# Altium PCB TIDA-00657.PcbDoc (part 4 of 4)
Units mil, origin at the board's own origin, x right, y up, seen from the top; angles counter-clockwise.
Board outline 2500 x 2500 mil, 4 copper layers (Top Layer, MidLayer1, MidLayer2, Bottom Layer); 149 components, 57 nets, 332 pads, 124 vias.
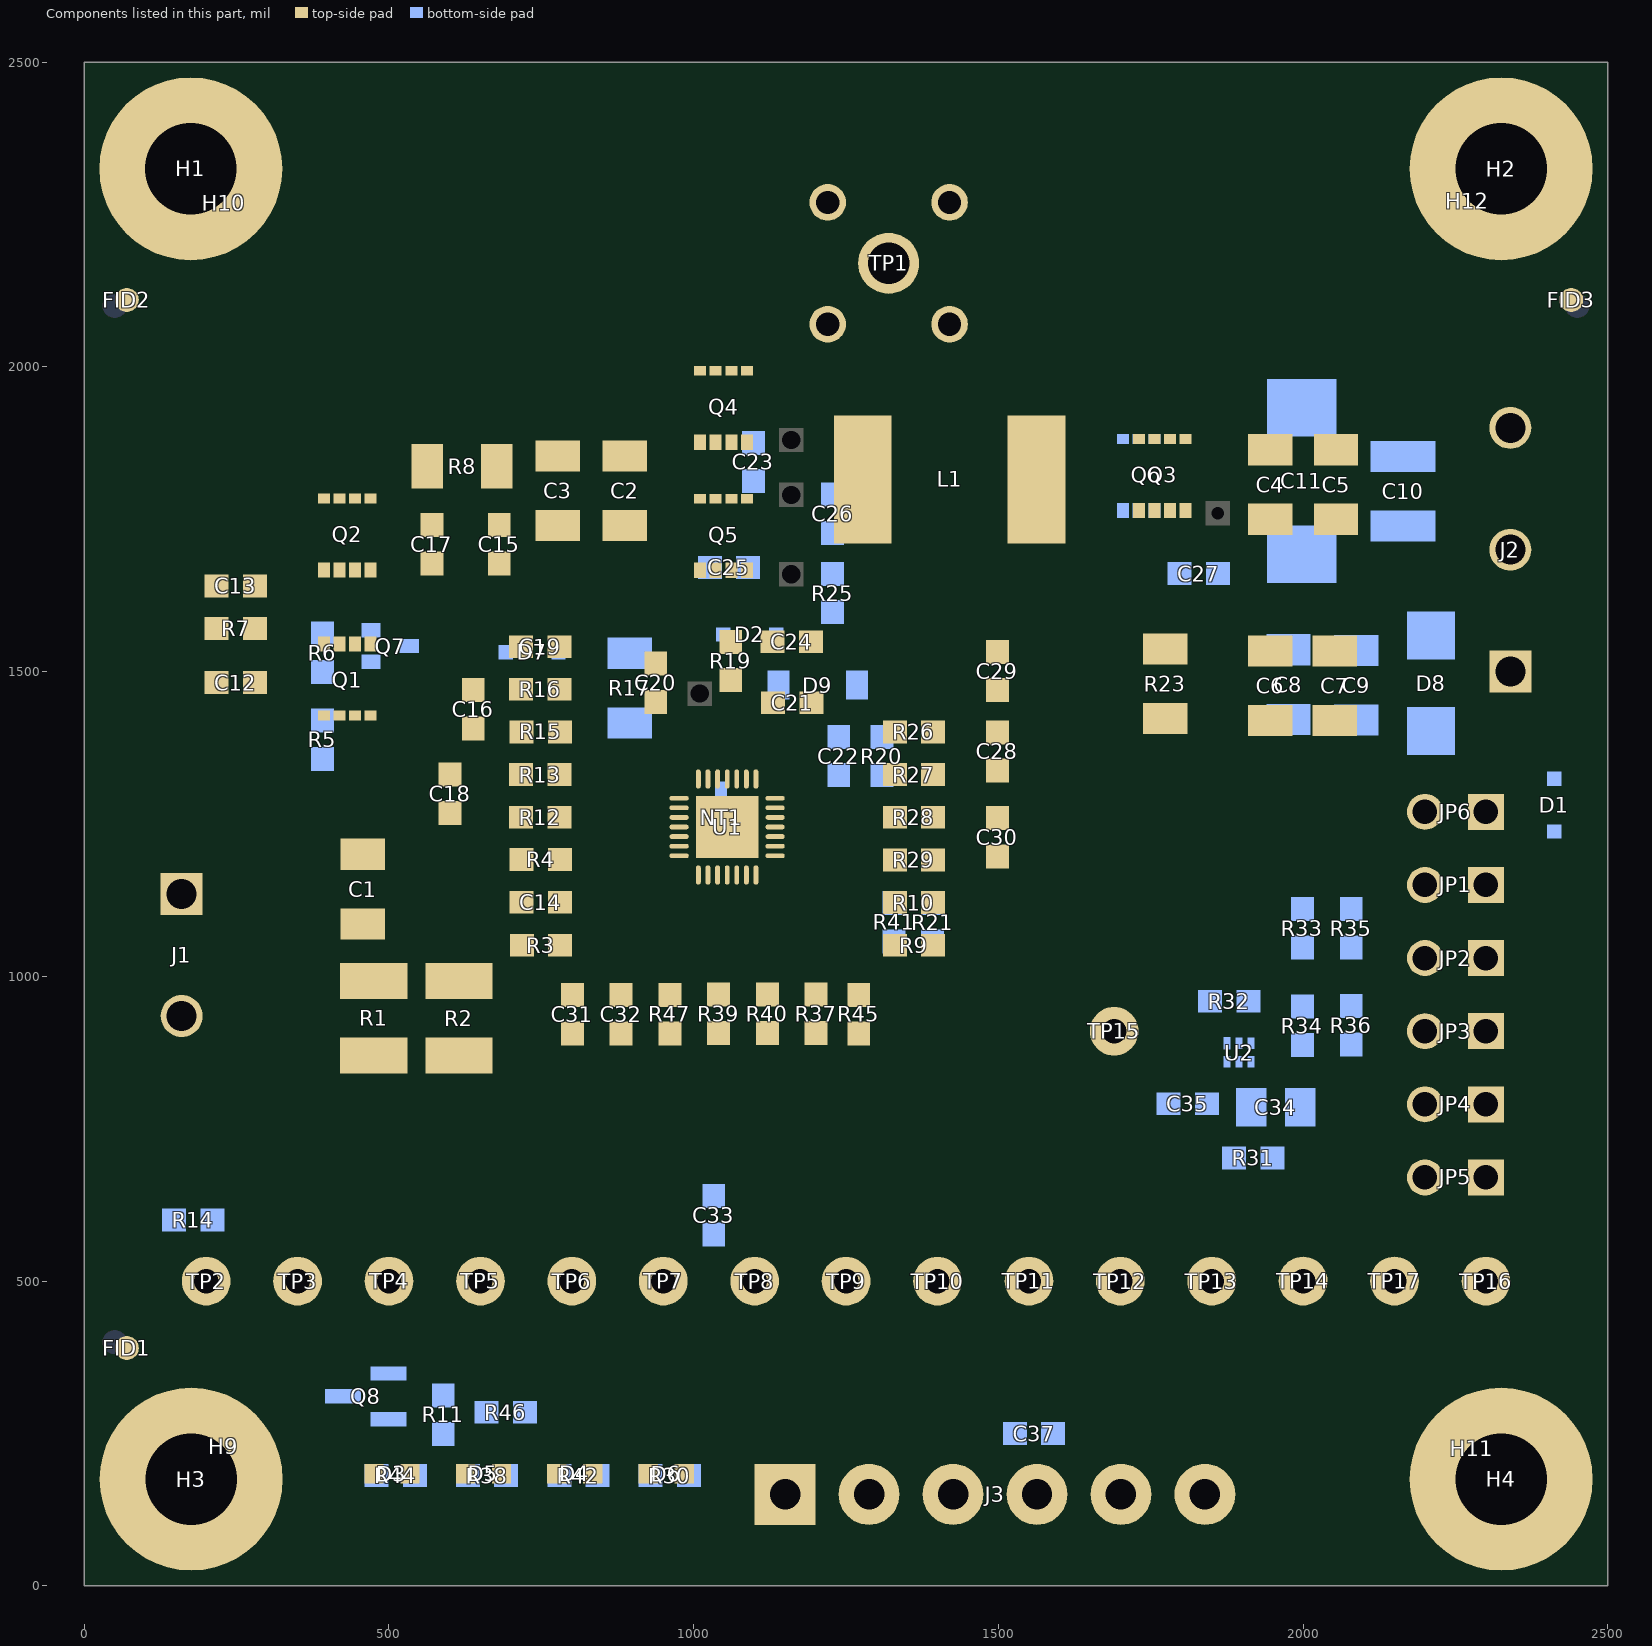
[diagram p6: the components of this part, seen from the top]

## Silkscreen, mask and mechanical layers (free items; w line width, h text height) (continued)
M10 Fab Notes:
  drawing of 212 lines, arcs and shapes, not listed
  text "DESIGN INFORMATION" at 12381.02,6810 h60
  text "(REFER ALSO ARRAY/PANEL PROFILING INFORMATION)" at 12019.46,6648.29 h60
  text "BOARD SIZE" at 11333.46,6644 h60
  text "2500MIL" at 11795.78,6516.18 h60
  text "X" at 12301.46,6516.18 h60
  text "2500MIL" at 12532.78,6516.18 h60
  text "Number of Layers :" at 11736.46,6319 h60
  text "4" at 12831.27,6309 h60
  text "MIN. TRACK WIDTH:" at 11736.46,6180 h60
  text "6" at 12832.7,6180 h60
  text "MIL" at 12987.46,6180 h60
  text "MIN. CLEARANCE:" at 11736.46,6048 h60
  text "6" at 12832.7,6048 h60
  text "MIL" at 12987.46,6048 h60
  text "MIN. VIA PAD SIZE:" at 11736.46,5916 h60
  text "12" at 12802.71,5916 h60
  text "MIL" at 12987.46,5916 h60
  text "0.05mm (2MIL)" at 12431.46,5774.29 h60
  text "MINIMUM ANNULAR RING" at 11407.23,5770 h60
  text "EXTERNAL" at 13139.46,5770 h60
  text "PER" at 11607.23,5652 h60
  text "IPC-D-275 CLASS 2 LEVEL C" at 11827.23,5652 h60
  text "MIL, HOLES" at 13315.46,5539.71 h60
  text "+/-" at 12923,5539 h60
  text "+/-" at 13777,5539 h60
  text "REGISTRATION TOLERANCES:" at 11407.23,5534 h60
  text "METAL" at 12607,5534 h60
  text "5" at 13183.2,5534 h60
  text "3" at 14016.2,5534 h60
  text "MIL" at 14132.46,5534 h60
  text "MATERIAL:" at 11332.46,5324.54 h60
  text "FR-4 High Tg" at 12318.9,5184.21 h60
  text "FR-408" at 11753.46,5175.64 h60
  text "X" at 12165.46,5175.64 h60
  text "OTHER" at 13241.46,5175.64 h60
  text "62 MIL (1.6mm) +/-10%" at 12073.56,5012.92 h60
  text "THICKNESS:" at 11407.23,5008.64 h60
  text "OTHER" at 13358.46,5008.64 h60
  text "1.2mm" at 13690.4,5003.64 h60
  text "X" at 13229.4,5002.64 h60
  text "TOLERANCE:" at 11407.23,4850.64 h60
  text "X" at 12246.53,4850.64 h60
  text "ANSI IPC-6012 TYPE 3 CLASS 2" at 12433.48,4850.64 h60
  text "OTHER +/-" at 12433.46,4694.64 h60
  text "BOW & TWIST:" at 11407.23,4537.64 h60
  text "X" at 12246.53,4537.64 h60
  text "ANSI IPC-6012 TYPE 3 CLASS 2" at 12433.48,4537.64 h60
  text "OTHER +/-" at 12433.46,4379.13 h60
  text "COPPER THICKNESS (FINISHED):" at 11332.46,4243.64 h60
  text "1.4MIL (1oz)" at 12212.46,4090.92 h60
  text "2MIL (1.4oz)" at 12979.46,4090.92 h60
  text "2.8MIL (2oz)" at 13706.46,4090.92 h60
  text "OUTER:" at 11689.46,4086.64 h60
  text "X" at 13580,4084 h60
  text "1.4MIL (1oz)" at 12212.46,3933.92 h60
  text "2.8MIL (2oz)" at 12979.46,3933.92 h60
  text "N/A" at 13706,3934.29 h60
  text "X" at 12855.42,3932.64 h60
  text "INNER SIGNAL:" at 11400.38,3929.64 h60
  text "DRILLING:" at 11332.46,3790.64 h60
  text "REFERENCE:" at 11407.23,3673.64 h60
  text "X" at 12055.46,3673.64 h60
  text "AS SHOWN" at 12242.46,3673.64 h60
  text "X" at 12956.46,3673.64 h60
  text "NC_DRILL FILES" at 13093.46,3673.64 h60
  text "PTH MIN COPPER THICKNESS:" at 11407.23,3515.64 h60
  text "X" at 12757.46,3515.64 h60
  text "1MIL" at 12894.46,3515.64 h60
  text "OTHER" at 13391.46,3515.64 h60
  text "BOARD FINISH:" at 11332.46,3356.64 h60
  text "SILKSCREEN:" at 11487.68,3238.64 h60
  text "X" at 12436.46,3238.64 h60
  text "TOP" at 12562.46,3238.64 h60
  text "X" at 12946.46,3238.64 h60
  text "BOTTOM" at 13073.46,3238.64 h60
  text "SILKSCREEN COLOR:" at 11487.68,3071.64 h60
  text "X" at 12435.42,3071.64 h60
  text "WHITE" at 12562.46,3071.64 h60
  text "OTHER" at 13073.46,3071.64 h60
  text "SOLDER RESIST COLOR:" at 11487.68,2901.64 h60
  text "X" at 12055.42,2742.44 h60
  text "GREEN" at 12182.46,2742.44 h60
  text "BLUE" at 12773.46,2742.44 h60
  text "OTHER" at 13311.46,2742.44 h60
  text "IMMERSION GOLD (ENIG)" at 12393.46,2553.92 h60
  text "ENEPIG" at 13731,2550.64 h60
  text "SURFACE FINISH:" at 11332.46,2549.64 h60
  text "X" at 12206.51,2549.64 h60
  text "IMM. TIN/SILVER OR EQUIV" at 11662,2392.64 h60
  text "OTHER" at 13093.46,2392.64 h60
  text "ARRAY/PANEL:" at 11332.46,2213.64 h60
  text "CUT AND TRIM PER MECH LAYER 1" at 12393.46,2209.35 h60
  text "N.C. ROUTE" at 12393.46,2057.64 h60
  text "X" at 13072.46,2057.64 h60
  text "V. SCORE" at 13259.46,2057.64 h60
  text "CERTIFICATION:" at 11332.46,1920.64 h60
  text "MATERIALS AND WORKMANSHIP FOR ALL PCBS" at 12057.46,1920.64 h60
  text "TO MEET OR EXCEED THE REQUIREMENTS OF:" at 12057.46,1822.64 h60
  text "X" at 11683.96,1686.13 h60
  text "ANSI IPC-A-600F CLASS ->" at 11822.96,1686.13 h60
  text "X" at 13462.02,1686.13 h60
  text "2" at 13580.96,1686.14 h60
  text "1" at 13265.96,1684.64 h60
  text "3" at 13934.96,1684.64 h60
  text "X" at 11686.02,1526.64 h60
  text "UL 94V-0" at 11822.96,1526.64 h60
  text "X" at 12498.02,1526.64 h60
  text "RoHS" at 12634.96,1526.64 h60
  text "OTHER" at 13279.36,1526.64 h60
  text "PER ORDER" at 13676.42,1526.64 h60
  text "ADDITIONAL REQUIREMENTS:" at 11332.46,1385.64 h60
  text "MICROSECTION:" at 11407.23,1270.64 h60
  text "YES" at 12312.96,1270.64 h60
  text "REQUIRED" at 13174.46,1114.49 h60
  text "BARE BOARD ELEC. TEST:" at 11407.23,1111.64 h60
  text "NONE" at 12712.96,1111.64 h60
  text "X" at 13047.46,1111.64 h60
  text "PER ORDER" at 13766.46,1111.64 h60
  text "MANUFACTURER'S UL:" at 11407.23,954.64 h60
  text "RAIL" at 12572.96,950.35 h60
  text "METAL" at 13064.77,950.35 h60
  text "X" at 13440,950 h60
  text "SILK" at 13576.46,950.35 h60
  text "Fab Notes" at 577,-858.49 h60
M11 Gerber Information:
  lines w10: -292,-930.17 6308,-930.17 ; -292,-726.83 6310,-726.83 ; -292,-523.5 -292,-1133.5 3713,-1133.5 6310,-1133.5 6310,-523.5 -291.5,-523.5 -291.5,-1133.5 1284,-1133.5 ; 2173,-1133.5 2173,-523.5 ; 3440,-726.83 3440,-523.5 ; 4280,-726.83 4280,-523.5 ; 4902,-1140 4902,-937.17
  text "ALL ARTWORK VIEWED FROM TOP SIDE" at -228.5,-655.67 h60
  text "BOARD #:" at 2248,-655.67 h60
  text "PWR583" at 2793.5,-655.67 h60
  text "REV:" at 3638,-655.67 h60
  text "B" at 3929.5,-655.67 h60
  text "SVN REV:" at 4476,-655.67 h60
  text "LAYER NAME =" at -228.5,-858.49 h60
  text "PLOT NAME =" at -228.5,-1064.34 h60
  text "GENERATED    :" at 2250,-1064.34 h60
  text "07/08/2014" at 3119.5,-1064.34 h60
  text "TEXAS INSTRUMENTS" at 5113,-1064.34 h60
M12 Stackup:
  lines w5: 11364,7531.25 14228,7531.25 ; 11364,7618.25 14228,7618.25 ; 11304,6974 ccw(c11332,6974) 11332,6946 14260,6946 ccw(c14260,6974) 14288,6974 14288,7695 ccw(c14260,7695) 14260,7723 11332,7723 ccw(c11332,7695) 11304,7695 11304,6974
  text "The Stackup Legend below this is static." at 11605.5,7874.5 h60
  text "If you change the stackup, update the Legend." at 11615.5,7784.5 h60
  text "Layer Stack Up Detail for: PWR583RevA.PcbDoc" at 11364,7641.12 h40
  text "Layer" at 11364,7585.75 h20
  text "Gerber" at 12356.51,7585.75 h20
  text "Copper" at 13076.85,7585.75 h20
  text "Dielectric" at 13829.83,7585.75 h20
  text "Name" at 11364,7545.75 h20
  text "Document" at 12356.51,7545.75 h20
  text "Thickness" at 13076.85,7545.75 h20
  text "Material" at 13829.83,7545.75 h20
  text "Top Solder Mask" at 11364,7488.28 h28
  text "(.GTS)" at 12356.51,7488.28 h28
  text "Solder Resist" at 13829.83,7488.28 h28
  text "Top Layer" at 11364,7407.34 h28
  text "(.GTL)" at 12356.51,7407.34 h28
  text "2.8mil" at 13076.85,7407.34 h28
  text "FR-4" at 13829.83,7366.88 h28
  text "MidLayer1" at 11364,7326.41 h28
  text "(.G1)" at 12356.51,7326.41 h28
  text "2.8mil" at 13076.85,7326.41 h28
  text "FR-4" at 13829.83,7285.94 h28
  text "MidLayer2" at 11364,7245.47 h28
  text "(.G2)" at 12356.51,7245.47 h28
  text "2.8mil" at 13076.85,7245.47 h28
  text "FR-4" at 13829.83,7205 h28
  text "Bottom Layer" at 11364,7164.53 h28
  text "(.GBL)" at 12356.51,7164.53 h28
  text "2.8mil" at 13076.85,7164.53 h28
  text "Bottom Solder Mask" at 11364,7083.59 h28
  text "(.GBS)" at 12356.51,7083.59 h28
  text "Solder Resist" at 13829.83,7083.59 h28
  text ".Layer_Name" at 577,-858.49 h60
M13 Component Bodies Top:
  text "Component Bodies Top" at 577,-858.49 h60
M14 Component Bodies Bottom:
  text "Component Bodies Bottom" at 577,-858.49 h60
M15 Courtyards Top:
  text ".Layer_Name" at 577,-858.49 h60
M16 Courtyards Bottom:
  text ".Layer_Name" at 577,-858.49 h60
Drill Drawing:
  circle w1: c4977.8,1979.37 r24.91
  circle w1: c4977.8,783.7 r14.95
  circle w1: c4977.8,783.7 r24.91
  lines w1: 4952.89,659.15 5002.71,659.15 4977.8,609.33 4952.89,659.15 ; 4952.89,908.25 5002.71,908.25 5002.71,958.07 4952.89,958.07 4952.89,908.25 ; 4952.89,1082.62 4977.8,1057.71 5002.71,1082.62 4977.8,1107.53 4952.89,1082.62 ; 4952.89,1207.17 4952.89,1219.62 4965.35,1232.08 4952.89,1244.53 4952.89,1256.99 4965.35,1256.99 4977.8,1244.53 4990.26,1256.99 5002.71,1256.99 5002.71,1244.53 4990.26,1232.08 5002.71,1219.62 5002.71,1207.17 4990.26,1207.17 4977.8,1219.62 4965.35,1207.17 4952.89,1207.17 ; 4952.89,1369.08 4965.35,1369.08 4965.35,1356.63 4990.26,1356.63 4990.26,1369.08 5002.71,1369.08 5002.71,1393.99 4990.26,1393.99 4990.26,1406.45 4965.35,1406.45 4965.35,1393.99 4952.89,1393.99 4952.89,1369.08 ; 4952.89,1506.09 4977.8,1518.54 5002.71,1506.09 4990.26,1531 5002.71,1555.91 4977.8,1543.45 4952.89,1555.91 4965.35,1531 4952.89,1506.09 ; 4952.89,1668 4965.35,1668 4977.8,1655.54 4990.26,1668 5002.71,1668 4990.26,1680.45 5002.71,1692.91 4990.26,1692.91 4977.8,1705.36 4965.35,1692.91 4952.89,1692.91 4965.35,1680.45 4952.89,1668 ; 4952.89,1854.82 5002.71,1854.82 4977.8,1805 4952.89,1854.82 ; 4952.89,2103.92 5002.71,2103.92 5002.71,2153.74 4952.89,2153.74 4952.89,2103.92 ; 4962.85,649.19 4992.75,649.19 4977.8,619.3 4962.85,649.19 ; 4962.85,918.21 4992.75,918.21 4992.75,948.11 4962.85,948.11 4962.85,918.21
  lines w12: 4885,564.5 7004.4,564.5 ; 4885,2208.54 7004.4,2208.54 ; 5255.67,415.04 5255.67,2358 ; 5612.78,415.04 5612.78,2358 ; 6274.79,415.04 6274.79,2358 ; 6559.14,415.04 6559.14,2358 ; 4885,415.04 7004.4,415.04 7004.4,2358 4885,2358 4885,415.04
  text "Symbol" at 4974.68,2253.38 h72
  text "Quantity" at 5300.51,2253.38 h72
  text "Finished Hole Size" at 5657.62,2253.38 h72
  text "Plated" at 6319.62,2253.38 h72
  text "Hole Type" at 6603.98,2253.38 h72
  text "9" at 5300.51,2103.92 h60
  text "7.87mil (0.200mm)" at 5657.62,2103.92 h60
  text "PTH" at 6319.62,2103.92 h60
  text "Round" at 6603.98,2103.92 h60
  text "115" at 5300.51,1954.46 h60
  text "12.00mil (0.305mm)" at 5657.62,1954.46 h60
  text "PTH" at 6319.62,1954.46 h60
  text "Round" at 6603.98,1954.46 h60
  text "1" at 5300.51,1805 h60
  text "20.00mil (0.508mm)" at 5657.62,1805 h60
  text "PTH" at 6319.62,1805 h60
  text "Round" at 6603.98,1805 h60
  text "4" at 5300.51,1655.54 h60
  text "30.00mil (0.762mm)" at 5657.62,1655.54 h60
  text "PTH" at 6319.62,1655.54 h60
  text "Round" at 6603.98,1655.54 h60
  text "4" at 5300.51,1506.09 h60
  text "38.00mil (0.965mm)" at 5657.62,1506.09 h60
  text "PTH" at 6319.62,1506.09 h60
  text "Round" at 6603.98,1506.09 h60
  text "16" at 5300.51,1356.63 h60
  text "40.00mil (1.016mm)" at 5657.62,1356.63 h60
  text "PTH" at 6319.62,1356.63 h60
  text "Round" at 6603.98,1356.63 h60
  text "12" at 5300.51,1207.17 h60
  text "40.16mil (1.020mm)" at 5657.62,1207.17 h60
  text "PTH" at 6319.62,1207.17 h60
  text "Round" at 6603.98,1207.17 h60
  text "5" at 5300.51,1057.71 h60
  text "49.21mil (1.250mm)" at 5657.62,1057.71 h60
  text "PTH" at 6319.62,1057.71 h60
  text "Round" at 6603.98,1057.71 h60
  text "6" at 5300.51,908.25 h60
  text "50.00mil (1.270mm)" at 5657.62,908.25 h60
  text "PTH" at 6319.62,908.25 h60
  text "Round" at 6603.98,908.25 h60
  text "1" at 5300.51,758.79 h60
  text "68.00mil (1.727mm)" at 5657.62,758.79 h60
  text "PTH" at 6319.62,758.79 h60
  text "Round" at 6603.98,758.79 h60
  text "4" at 5300.51,609.33 h60
  text "150.00mil (3.810mm)" at 5657.62,609.33 h60
  text "PTH" at 6319.62,609.33 h60
  text "Round" at 6603.98,609.33 h60
  text "177 Total" at 5300.51,459.87 h60
  text "Drill Drawing" at 577,-858.49 h60

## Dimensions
0,0 to 2500,0 on M2 Board Dimensions
0,0 to 0,2500 on M2 Board Dimensions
